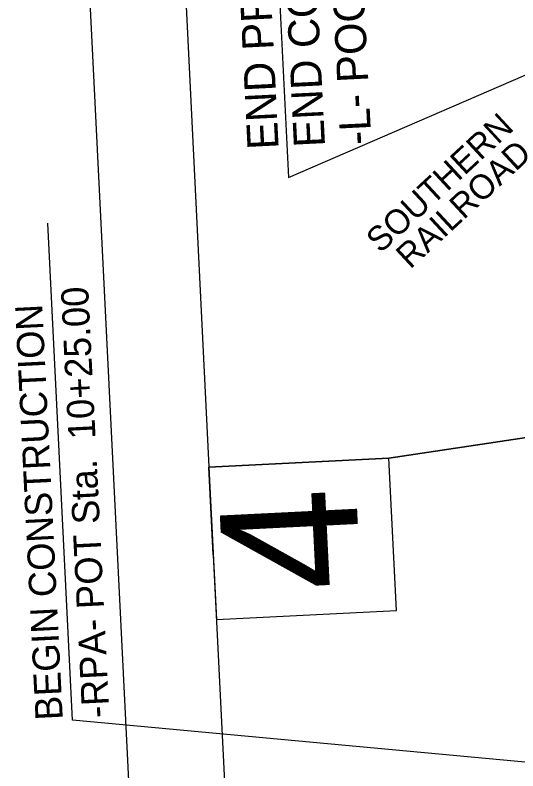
# Model space of a CAD drawing. Extents: x 1805231 to 1809482, y 908883 to 918297.
# Drawn here: x 1806964 to 1807610, y 914790 to 915762 of the extents above; entities that cross this region are included whole.
import ezdxf

# ---------------------------------------------------------------- set-up
doc = ezdxf.new("R2010")
doc.units = 0
for name, color, linetype in [('Prop Horizontal Alignment Station Label', 7, 'Continuous'), ('Prop Leader Line Medium', 7, 'Continuous'), ('Prop Shade Medium', 7, 'Continuous'), ('Scratch_Level_0', 7, 'Continuous')]:
    doc.layers.add(name, color=color, linetype=linetype)

msp = doc.modelspace()

# ---------------------------------------------------------------- linework, layer by layer
at = {"layer": 'Prop Horizontal Alignment Station Label'}
for p, q in [((1807279.71, 916259.84), (1807314.78, 915553.48)), ((1807314.78, 915553.48), (1807756.13, 915744.83)), ((1807037.39, 914855.72), (1807005.65, 915495.02)), ((1807657.5, 914797.84), (1807037.39, 914855.72))]:
    msp.add_line(p, q, dxfattribs=at)
at = {"layer": 'Prop Shade Medium'}
for points in [[(1808257.25, 915314.81), (1808192.53, 916618.4), (1807143.82, 916566.34), (1807143.82, 916566.34), (1807144.37, 916566.36), (1807218.2, 915068.18), (1807212.6, 915180.97), (1807443.97, 915192.45)], [(1807282.66, 913769.83), (1808331.37, 913821.9), (1808257.25, 915314.81), (1807443.97, 915192.45), (1807212.6, 915180.97), (1807218.2, 915068.18)], [(1807212.6, 915180.97), (1807222.32, 914985.29), (1807453.68, 914996.78), (1807443.97, 915192.45)]]:
    msp.add_lwpolyline(points, close=True, dxfattribs=at)
at = {"layer": 'Scratch_Level_0'}
msp.add_lwpolyline([(1807178.45, 913396.62), (1807021.12, 916565.54), (1808570.99, 916642.49), (1808728.32, 913473.56)], close=True, dxfattribs=at)

# ---------------------------------------------------------------- texts
at = {"layer": 'Prop Horizontal Alignment Station Label'}
for s, height, rotation, p in [('END PROJECT BP7.R001', 40, 92.84219, (1807302.38, 915590.5)), ('-L- POC Sta.  32+50.00', 40, 92.84219, (1807421.61, 915596.42)), ('END CONSTRUCTION', 40, 92.84219, (1807361.99, 915593.46)), ('-RPA- POT Sta.  10+25.00', 35, 92.84221, (1807084.87, 914859.37)), ('BEGIN CONSTRUCTION', 35, 92.84221, (1807024.94, 914856.39))]:
    msp.add_text(s, height=height, rotation=rotation, dxfattribs=at).set_placement(p)
at = {"layer": 'Prop Leader Line Medium'}
for s, p in [('SOUTHERN', (1807432.99, 915455.13)), ('RAILROAD', (1807471.37, 915434.88))]:
    msp.add_text(s, height=31.5, rotation=42.84089, dxfattribs=at).set_placement(p)
at = {"layer": 'Prop Shade Medium'}
msp.add_text('4', height=176.6, rotation=92.84219, dxfattribs=at).set_placement((1807408.13, 915026.12))

doc.saveas('drawing.dxf')
